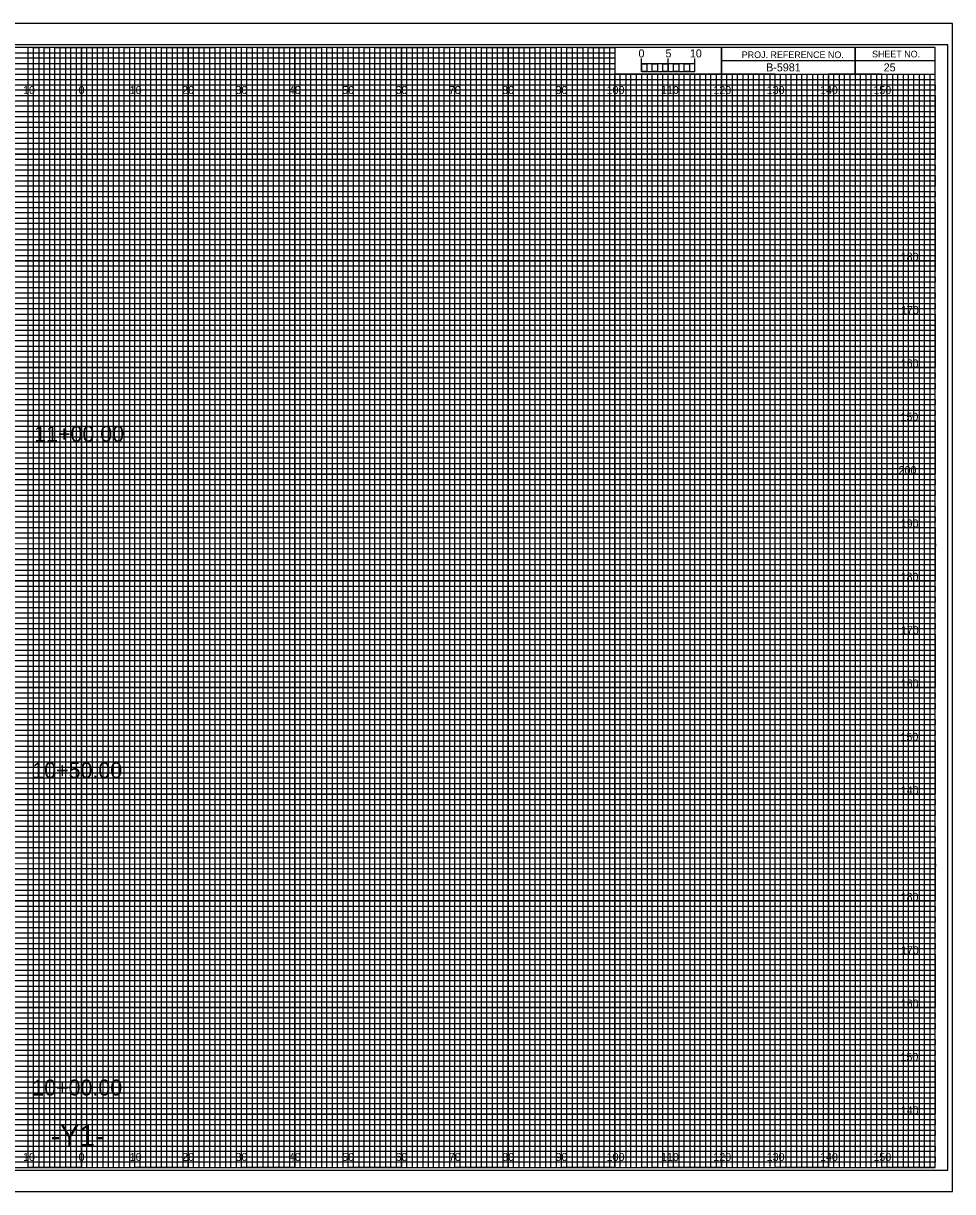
# Model space of a CAD drawing. Extents: x -13 to 323, y -5 to 654.
# Drawn here: x 149.1 to 323.3, y -4.5 to 214.5 of the extents above; entities that cross this region are included whole.
import ezdxf

# ---------------------------------------------------------------- set-up
doc = ezdxf.new("R2010")
doc.units = 0
for name, color, linetype in [('Exist Cross Section Cell', 7, 'Continuous'), ('Exist XS Center Line Elevation Label', 7, 'Continuous'), ('Exist XS Ground Line', 7, 'Continuous'), ('Prop CMT Concrete Structures', 7, 'Continuous'), ('Prop CMT Guardrail Graphics', 7, 'Continuous'), ('Prop CMT Pvmt Course 1', 7, 'Continuous'), ('Prop CMT Pvmt Course 2', 7, 'Continuous'), ('Prop CMT Pvmt Course 3', 7, 'Continuous'), ('Prop CMT Pvmt Surface', 7, 'Continuous'), ('Prop CMT Shld Paved Course 1', 7, 'Continuous'), ('Prop CMT Shld Paved Course 2', 7, 'Continuous'), ('Prop CMT Shld Paved Course 3', 7, 'Continuous'), ('Prop CMT Subgrade Earthwork', 7, 'Continuous'), ('Prop XS Ditch Standard Text', 7, 'Continuous'), ('Prop XS SE Text', 7, 'Continuous'), ('Prop XS Side Slope Text', 7, 'Continuous'), ('Scratch_Level_0', 7, 'Continuous')]:
    doc.layers.add(name, color=color, linetype=linetype)

msp = doc.modelspace()

# ---------------------------------------------------------------- linework, layer by layer
at = {"layer": 'Exist XS Center Line Elevation Label'}
for points in [[(145, 0), (155, 0), (155, 210), (165, 210), (165, 0), (175, 0), (175, 210), (185, 210), (185, 0), (195, 0), (195, 210), (205, 210), (205, 0), (215, 0), (215, 210), (225, 210), (225, 0), (235, 0), (235, 210), (245, 210), (245, 0), (255, 0), (255, 210), (259.93, 210), (260, 210), (260, 205), (264.99, 205), (264.99, 0), (275, 0), (275, 205), (285, 205), (285, 0), (295, 0), (295, 205), (305, 205), (305, 0), (315, 0), (315, 205)], [(0, 205), (275, 205)], [(0, 185), (320, 185), (320, 195), (0, 195)], [(0, 165), (320, 165), (320, 175), (0, 175)], [(0, 145), (320, 145), (320, 155), (0, 155)], [(0, 125), (320, 125), (320, 135), (0, 135)], [(0, 105), (320, 105), (320, 115), (0, 115)], [(0, 85), (320, 85), (320, 95), (0, 95)], [(0, 65), (320, 65), (320, 75), (0, 75)], [(0, 45), (320, 45), (320, 55), (0, 55)], [(0, 25), (320, 25), (320, 35), (0, 35)], [(0, 5), (320, 5), (320, 15), (0, 15)]]:
    msp.add_lwpolyline(points, dxfattribs=at)
at = {"layer": 'Exist XS Ground Line'}
for p, q in [((150, 210), (140, 210)), ((150, 0), (150, 210)), ((170, 210), (160, 210)), ((160, 210), (160, 0)), ((170, 0), (170, 210)), ((190, 210), (180, 210)), ((180, 210), (180, 0)), ((190, 0), (190, 210)), ((210, 210), (200, 210)), ((200, 210), (200, 0)), ((210, 0), (210, 210)), ((230, 210), (220, 210)), ((220, 210), (220, 0)), ((230, 0), (230, 210)), ((250, 210), (240, 210)), ((240, 210), (240, 0)), ((250, 0), (250, 210)), ((260, 210), (260, 0)), ((270, 0), (270, 205)), ((290, 205), (280, 205)), ((280, 205), (280, 0)), ((290, 0), (290, 205)), ((310, 205), (300, 205)), ((300, 205), (300, 0)), ((310, 0), (310, 205)), ((160, 0), (150, 0)), ((180, 0), (170, 0)), ((200, 0), (190, 0)), ((220, 0), (210, 0)), ((240, 0), (230, 0)), ((260, 0), (250, 0)), ((280, 0), (270, 0)), ((300, 0), (290, 0)), ((320, 0), (310, 0)), ((320, 0), (320, 0))]:
    msp.add_line(p, q, dxfattribs=at)
for points in [[(0, 200), (320, 200), (320, 190), (0, 190)], [(0, 180), (320, 180), (320, 170), (0, 170)], [(0, 160), (320, 160), (320, 150), (0, 150)], [(0, 140), (320, 140), (320, 130), (0, 130)], [(0, 120), (320, 120), (320, 110), (0, 110)], [(0, 100), (320, 100), (320, 90), (0, 90)], [(0, 80), (320, 80), (320, 70), (0, 70)], [(0, 60), (320, 60), (320, 50), (0, 50)], [(0, 40), (320, 40), (320, 30), (0, 30)], [(0, 20), (320, 20), (320, 10), (0, 10)]]:
    msp.add_lwpolyline(points, dxfattribs=at)
at = {"layer": 'Prop CMT Pvmt Course 1'}
for p, q in [((323.3, 214.5), (-13.4, 214.5)), ((-13.4, -4.5), (323.3, -4.5))]:
    msp.add_line(p, q, dxfattribs=at)
at = {"layer": 'Prop CMT Pvmt Course 2'}
msp.add_lwpolyline([(-13.4, -4.5), (323.3, -4.5), (323.3, 214.5), (-13.4, 214.5)], close=True, dxfattribs=at)
at = {"layer": 'Prop CMT Pvmt Course 3'}
msp.add_lwpolyline([(-10.8, -0.5), (322.4, -0.5), (322.4, 210.5), (-10.8, 210.5)], close=True, dxfattribs=at)
at = {"layer": 'Prop CMT Shld Paved Course 1'}
for p, q in [((305, 210), (305, 205)), ((305, 205), (305, 210)), ((280, 207.5), (280, 205)), ((320, 207.49), (280, 207.49)), ((280, 205), (320, 205))]:
    msp.add_line(p, q, dxfattribs=at)
for points in [[(320, 210), (0, 210), (0, 0), (320, 0)], [(280, 210), (260, 210), (260, 205.03), (280, 205.03)], [(320, 210), (280, 210), (280, 205), (320, 205)]]:
    msp.add_lwpolyline(points, close=True, dxfattribs=at)
at = {"layer": 'Prop CMT Shld Paved Course 2'}
for p, q in [((267, 205), (266.01, 205)), ((266.01, 205), (266.01, 0)), ((267, 0), (267, 205)), ((269, 205), (268, 205)), ((268, 205), (268, 0)), ((269, 0), (269, 205)), ((266.01, 0), (265, 0)), ((268, 0), (267, 0))]:
    msp.add_line(p, q, dxfattribs=at)
for points in [[(150, 0), (151, 0), (151, 210), (152, 210), (152, 0)], [(152, 0), (153, 0), (153, 210), (154, 210), (154, 0)], [(155, 0), (156, 0), (156, 210), (157, 210), (157, 0)], [(157, 0), (158, 0), (158, 210), (159, 210), (159, 0)], [(160, 0), (161, 0), (161, 210), (162, 210), (162, 0)], [(162, 0), (163, 0), (163, 210), (164, 210), (164, 0)], [(165, 0), (166, 0), (166, 210), (167, 210), (167, 0)], [(167, 0), (168, 0), (168, 210), (169, 210), (169, 0)], [(170, 0), (171, 0), (171, 210), (172, 210), (172, 0)], [(172, 0), (173, 0), (173, 210), (174, 210), (174, 0)], [(175, 0), (176, 0), (176, 210), (177, 210), (177, 0)], [(177, 0), (178, 0), (178, 210), (179, 210), (179, 0)], [(180, 0), (181, 0), (181, 210), (182, 210), (182, 0)], [(182, 0), (183, 0), (183, 210), (184, 210), (184, 0)], [(185, 0), (186, 0), (186, 210), (187, 210), (187, 0)], [(187, 0), (188, 0), (188, 210), (189, 210), (189, 0)], [(190, 0), (191, 0), (191, 210), (192, 210), (192, 0)], [(192, 0), (193, 0), (193, 210), (194, 210), (194, 0)], [(195, 0), (196, 0), (196, 210), (197, 210), (197, 0)], [(197, 0), (198, 0), (198, 210), (199, 210), (199, 0)], [(200, 0), (201, 0), (201, 210), (202, 210), (202, 0)], [(202, 0), (203, 0), (203, 210), (204, 210), (204, 0)], [(205, 0), (206, 0), (206, 210), (207, 210), (207, 0)], [(207, 0), (208, 0), (208, 210), (209, 210), (209, 0)], [(210, 0), (211, 0), (211, 210), (212, 210), (212, 0)], [(212, 0), (213, 0), (213, 210), (214, 210), (214, 0)], [(215, 0), (216, 0), (216, 210), (217, 210), (217, 0)], [(217, 0), (218, 0), (218, 210), (219, 210), (219, 0)], [(220, 0), (221, 0), (221, 210), (222, 210), (222, 0)], [(222, 0), (223, 0), (223, 210), (224, 210), (224, 0)], [(225, 0), (226, 0), (226, 210), (227, 210), (227, 0)], [(227, 0), (228, 0), (228, 210), (229, 210), (229, 0)], [(230, 0), (231, 0), (231, 210), (232, 210), (232, 0)], [(232, 0), (233, 0), (233, 210), (234, 210), (234, 0)], [(235, 0), (236, 0), (236, 210), (237, 210), (237, 0)], [(237, 0), (238, 0), (238, 210), (239, 210), (239, 0)], [(240, 0), (241, 0), (241, 210), (242, 210), (242, 0)], [(242, 0), (243, 0), (243, 210), (244, 210), (244, 0)], [(245, 0), (246, 0), (246, 210), (247, 210), (247, 0)], [(247, 0), (248, 0), (248, 210), (249, 210), (249, 0)], [(250, 0), (251, 0), (251, 210), (252, 210), (252, 0)], [(252, 0), (253, 0), (253, 210), (254, 210), (254, 0)], [(255, 0), (256, 0), (256, 210), (257, 210), (257, 0)], [(257, 0), (258, 0), (258, 210), (259, 210), (259, 0)], [(260, 0), (261, 0), (261, 205), (262.02, 205), (262.02, 0)], [(262, 0), (263, 0), (263, 205), (263.99, 205), (263.99, 0)], [(270, 0), (270.98, 0), (270.98, 205), (272, 205), (272, 0)], [(272, 0), (273, 0), (273, 205), (274.05, 205), (274.05, 0)], [(275, 0), (276, 0), (276, 205), (277, 205), (277, 0)], [(277, 0), (278, 0), (278, 205), (279, 205), (279, 0)], [(280, 0), (281, 0), (281, 205), (282, 205), (282, 0)], [(282, 0), (283, 0), (283, 205), (284, 205), (284, 0)], [(285, 0), (286, 0), (286, 205), (287, 205), (287, 0)], [(287, 0), (288, 0), (288, 205), (289, 205), (289, 0)], [(290, 0), (291, 0), (291, 205), (292, 205), (292, 0)], [(292, 0), (293, 0), (293, 205), (294, 205), (294, 0)], [(295, 0), (296, 0), (296, 205), (297, 205), (297, 0)], [(297, 0), (298, 0), (298, 205), (299, 205), (299, 0)], [(300, 0), (301, 0), (301, 205), (302, 205), (302, 0)], [(302, 0), (303, 0), (303, 205), (304, 205), (304, 0)], [(305, 0), (306, 0), (306, 205), (307, 205), (307, 0)], [(307, 0), (308, 0), (308, 205), (309, 205), (309, 0)], [(310, 0), (311, 0), (311, 205), (312, 205), (312, 0)], [(312, 0), (313, 0), (313, 205), (314, 205), (314, 0)], [(315, 0), (316, 0), (316, 205), (317, 205), (317, 0)], [(317, 0), (318, 0), (318, 205), (319, 205), (319, 0)]]:
    msp.add_lwpolyline(points, dxfattribs=at)
at = {"layer": 'Prop CMT Shld Paved Course 3'}
for p, q in [((265, 205.49), (265, 207.9)), ((265, 206.9), (265, 207.9)), ((270, 205.49), (270, 207.9)), ((275, 205.49), (275, 207.9)), ((275, 206.9), (275, 207.9))]:
    msp.add_line(p, q, dxfattribs=at)
for points in [[(275, 206.9), (265, 206.9), (265, 205.49), (275, 205.49)], [(265, 206.9), (266, 206.9), (266, 205.49), (265, 205.49)], [(267, 206.9), (268, 206.9), (268, 205.49), (267, 205.49)], [(269, 206.9), (270, 206.9), (270, 205.49), (269, 205.49)], [(271, 206.9), (272, 206.9), (272, 205.49), (271, 205.49)], [(273, 206.9), (274, 206.9), (274, 205.49), (273, 205.49)]]:
    msp.add_lwpolyline(points, close=True, dxfattribs=at)
at = {"layer": 'Prop CMT Subgrade Earthwork'}
for p, q in [((150, 0), (150, 210)), ((160, 0), (160, 210)), ((170, 0), (170, 210)), ((180, 0), (180, 210)), ((190, 0), (190, 210)), ((200, 0), (200, 210)), ((210, 0), (210, 210)), ((220, 0), (220, 210)), ((230, 0), (230, 210)), ((240, 0), (240, 210)), ((250, 0), (250, 210)), ((260, 0), (260, 204.69)), ((270, 0), (270, 204.69)), ((280, 0), (280, 204.69)), ((290, 0), (290, 204.69)), ((300, 0), (300, 204.69)), ((310, 0), (310, 204.69)), ((0, 200), (320, 200)), ((0, 190), (320, 190)), ((0, 180), (320, 180)), ((0, 170), (320, 170)), ((0, 160), (320, 160)), ((0, 150), (320, 150)), ((0, 140), (320, 140)), ((0, 130), (320, 130)), ((0, 120), (320, 120)), ((0, 110), (320, 110)), ((0, 100), (320, 100)), ((0, 90), (320, 90)), ((0, 80), (320, 80)), ((0, 70), (320, 70)), ((0, 60), (320, 60)), ((0, 50), (320, 50)), ((0, 40), (320, 40)), ((0, 30), (320, 30)), ((0, 20), (320, 20)), ((0, 10), (320, 10))]:
    msp.add_line(p, q, dxfattribs=at)
at = {"layer": 'Scratch_Level_0'}
for p, q in [((0, 209), (260, 209)), ((260, 209), (260, 207.98)), ((260, 207.98), (0, 207.98)), ((0, 207), (260, 207)), ((260, 205.89), (0, 205.89)), ((260, 207), (260, 205.89)), ((0, 204), (320, 204))]:
    msp.add_line(p, q, dxfattribs=at)
for points in [[(0, 203), (270, 203), (320, 203), (320, 202), (0, 202)], [(0, 201), (320, 201), (320, 199), (0, 199)], [(0, 198), (320, 198), (320, 197), (0, 196.98)], [(0, 196), (320, 196), (320, 194), (0, 194)], [(0, 193), (320, 193), (320, 192), (0, 192)], [(0, 191), (320, 191), (320, 189), (0, 189)], [(0, 188), (320, 188), (320, 187), (0, 187)], [(0, 186), (320, 186), (320, 184), (0, 184)], [(0, 183), (320, 183), (320, 182), (0, 182)], [(0, 181), (320, 181), (320, 179), (0, 179)], [(0, 178), (320, 178), (320, 177), (0, 177)], [(0, 176), (320, 176), (320, 173.95), (320, 173), (320, 172), (0, 172)], [(0, 174), (320, 174), (320, 173), (0, 173)], [(0, 171), (320, 171), (320, 169), (0, 169.03)], [(0, 169.03), (320, 169), (320, 168), (0, 168)], [(0, 167), (320, 167), (320, 166), (0, 166)], [(0, 164), (320, 164), (320, 163), (0, 163)], [(0, 162), (320, 162), (320, 161), (0, 161)], [(-0.07, 158.89), (320, 158.89), (320, 157.88), (-0.07, 157.88)], [(0, 157), (320, 157), (320, 156), (0, 156)], [(0, 154), (320, 154), (320, 153), (0, 153)], [(0, 152), (320, 152), (320, 151), (0, 151)], [(0, 149), (320, 149), (320, 148), (0, 148)], [(0, 147), (320, 147), (320, 146), (0, 146)], [(0, 144), (320, 144), (320, 143), (0, 143)], [(0, 142), (320, 142), (320, 141), (0, 141)], [(0, 139), (320, 139), (319.99, 137.98), (0, 138)], [(0, 137), (320, 137), (320, 136), (0, 136)], [(0, 134), (320, 134), (320, 133), (0, 133)], [(0, 132), (320, 132), (320, 131), (0, 131)], [(0, 129), (320, 129), (320, 128), (0, 128)], [(0, 127), (320, 127), (320, 126), (0, 126)], [(0, 124), (320, 124), (320, 123), (0, 123)], [(0, 122), (320, 122), (320, 121), (0, 121)], [(0, 119), (320, 119), (320, 118), (0, 118)], [(0, 116.99), (320.07, 116.91), (320, 116), (0, 116)], [(0, 114), (320, 114), (320, 113), (0, 113)], [(0, 112), (320, 112), (320, 111), (0, 111)], [(0, 109), (320, 109), (320, 108), (0, 108)], [(0, 107), (320, 107), (320, 106), (0, 106)], [(0, 104), (320, 104), (320, 103), (0, 103)], [(0, 102), (320, 102), (320, 101), (0, 101)], [(0, 99), (320, 99), (320, 98), (0, 98)], [(0, 97), (320, 97), (320, 96), (0, 96)], [(0, 94), (320, 94), (320, 93), (0, 93)], [(0, 92), (320, 92), (320, 91), (0, 91)], [(0, 89), (320, 89), (320, 88), (0, 88)], [(0, 87), (320, 87), (320, 86), (0, 86)], [(0, 84), (320, 84), (320, 83), (0, 83)], [(0, 82), (320, 82), (320, 81), (0, 81)], [(0, 79), (320, 79), (319.99, 77.98), (0, 78)], [(0, 77), (320, 77), (320, 76), (0, 76)], [(0, 74), (320, 74), (320, 73), (0, 73)], [(0, 72), (320, 72), (320, 71), (0, 71)], [(0, 69), (320, 69), (320, 68), (0, 68)], [(0, 67), (320, 67), (320, 66), (0, 66)], [(0, 64), (320, 64), (320, 63), (0, 63)], [(0, 62), (320, 62), (320, 61), (0, 61)], [(0, 59), (320, 59), (320, 58), (0, 58)], [(0, 56.99), (320.07, 56.91), (320, 56), (0, 56)], [(0, 54), (320, 54), (320, 53), (0, 53)], [(0, 52), (320, 52), (320, 51), (0, 51)], [(0, 49), (320, 49), (320, 48), (0, 48)], [(0, 47), (320, 47), (320, 46), (0, 46)], [(0, 44), (320, 44), (320, 43), (0, 43)], [(0, 42), (320, 42), (320, 41), (0, 41)], [(0, 39), (320, 39), (320, 38), (0, 38)], [(0, 37), (320, 37), (320, 36), (0, 36)], [(0, 34), (320, 34), (320, 33), (0, 33)], [(0, 32), (320, 32), (320, 31), (0, 31)], [(0, 29), (320, 29), (320, 28), (0, 28)], [(0, 27), (320, 27), (320, 26), (0, 26)], [(0, 24), (320, 24), (320, 23), (0, 23)], [(0, 22), (320, 22), (320, 21), (0, 21)], [(0, 19), (320, 19), (320, 18), (0, 18)], [(0, 17), (320, 17), (320, 16), (0, 16)], [(0, 14), (320, 14), (320, 13), (0, 13)], [(0, 12), (320, 12), (320, 11), (0, 11)], [(0, 9), (320, 9), (320, 8), (0, 8)], [(0, 7), (320, 7), (320, 6), (0, 6)], [(0, 4), (320, 4), (320, 3), (0, 3)], [(0, 2), (320, 2), (320, 1), (0, 1)]]:
    msp.add_lwpolyline(points, dxfattribs=at)

# ---------------------------------------------------------------- texts
at = {"layer": 'Exist Cross Section Cell'}
for s, p in [('10', (149.04, 201.25)), ('0', (159.45, 201.25)), ('0', (159.45, 201.25)), ('10', (169.04, 201.25)), ('20', (178.86, 201.25)), ('30', (188.86, 201.25)), ('40', (198.86, 201.25)), ('50', (208.86, 201.25)), ('60', (218.86, 201.25)), ('70', (228.86, 201.25)), ('80', (238.86, 201.25)), ('90', (248.86, 201.25)), ('100', (258.44, 201.25)), ('110', (268.62, 201.25)), ('120', (278.44, 201.25)), ('130', (288.44, 201.25)), ('140', (298.44, 201.25)), ('150', (308.44, 201.25)), ('10', (149.04, 1.25)), ('0', (159.45, 1.25)), ('0', (159.45, 1.25)), ('10', (169.04, 1.25)), ('20', (178.86, 1.25)), ('30', (188.86, 1.25)), ('40', (198.86, 1.25)), ('50', (208.86, 1.25)), ('60', (218.86, 1.25)), ('70', (228.86, 1.25)), ('80', (238.86, 1.25)), ('90', (248.86, 1.25)), ('100', (258.44, 1.25)), ('110', (268.62, 1.25)), ('120', (278.44, 1.25)), ('130', (288.44, 1.25)), ('140', (298.44, 1.25)), ('150', (308.44, 1.25))]:
    msp.add_text(s, height=1.5, dxfattribs=at).set_placement(p)
at = {"layer": 'Prop CMT Concrete Structures'}
for s, p in [('11+00.00', (151.13, 136.06)), ('10+50.00', (150.77, 72.99)), ('10+00.00', (150.77, 13.51))]:
    msp.add_text(s, height=3, dxfattribs=at).set_placement(p)
at = {"layer": 'Prop CMT Guardrail Graphics'}
for s, p in [('180', (313.55, 170)), ('170', (313.61, 160)), ('160', (313.57, 150)), ('150', (313.52, 140)), ('200', (313.17, 130)), ('190', (313.57, 120)), ('180', (313.55, 110)), ('170', (313.61, 100)), ('160', (313.57, 90)), ('150', (313.52, 80)), ('140', (313.57, 70)), ('180', (313.55, 50)), ('170', (313.61, 40)), ('160', (313.57, 30)), ('150', (313.52, 20)), ('140', (313.57, 10))]:
    msp.add_text(s, height=1.5, dxfattribs=at).set_placement(p)
at = {"layer": 'Prop CMT Pvmt Surface'}
for s, p in [('5', (269.47, 208.12)), ('10', (274.04, 208.12))]:
    msp.add_text(s, height=1.5, dxfattribs=at).set_placement(p)
at = {"layer": 'Prop CMT Shld Paved Course 1'}
for s, p in [('PROJ. REFERENCE NO.', (283.77, 207.99)), ('SHEET NO.', (308.19, 208.12))]:
    msp.add_text(s, height=1.25, dxfattribs=at).set_placement(p)
at = {"layer": 'Prop CMT Shld Paved Course 3'}
msp.add_text('0', height=1.5, dxfattribs=at).set_placement((264.41, 208.12))
at = {"layer": 'Prop XS Ditch Standard Text'}
msp.add_text('-Y1-', height=4, dxfattribs=at).set_placement((154.21, 4))
at = {"layer": 'Prop XS SE Text'}
msp.add_text(' B-5981', height=1.5, dxfattribs=at).set_placement((287.79, 205.5))
at = {"layer": 'Prop XS Side Slope Text'}
msp.add_text('25', height=1.5, dxfattribs=at).set_placement((310.38, 205.5))

doc.saveas('drawing.dxf')
